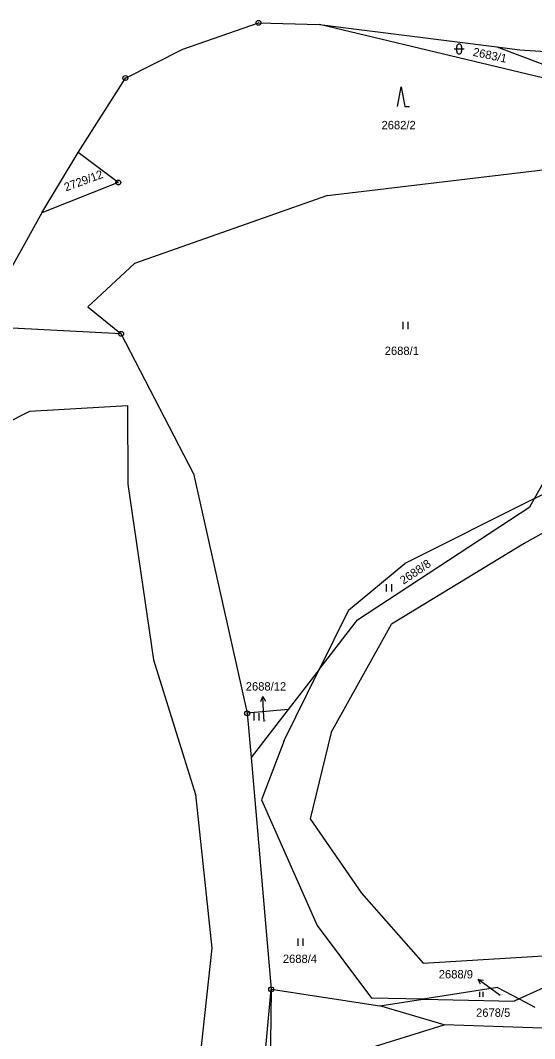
# Model space of a CAD drawing. Extents: x -736345 to -729997, y -1130177 to -1122501.
# Drawn here: x -734447.9 to -734343.4, y -1125281.1 to -1125074.1 of the extents above; entities that cross this region are included whole.
import ezdxf

# ---------------------------------------------------------------- set-up
doc = ezdxf.new("R2010")
doc.units = 0
for name, color, linetype in [('Vrstva 1', 7, 'Continuous'), ('Vrstva 16', 7, 'Continuous'), ('Vrstva 18', 7, 'Continuous'), ('Vrstva 25', 7, 'Continuous'), ('Vrstva 4', 7, 'Continuous')]:
    doc.layers.add(name, color=color, linetype=linetype)

msp = doc.modelspace()

# ---------------------------------------------------------------- linework, layer by layer
at = {"layer": 'Vrstva 1'}
for points in [[(-734414.96, -1125079.9), (-734399.56, -1125074.56)], [(-734399.56, -1125074.56), (-734387.19, -1125074.9)], [(-734321.46, -1125090.64), (-734387.19, -1125074.9)], [(-734387.19, -1125074.9), (-734351.13, -1125079.46)], [(-734426.61, -1125085.79), (-734414.96, -1125079.9)], [(-734351.13, -1125079.46), (-734346.43, -1125080.06)], [(-734351.13, -1125079.46), (-734321.46, -1125090.64)], [(-734346.43, -1125080.06), (-734331.84, -1125081)], [(-734436.2, -1125100.93), (-734426.61, -1125085.79)], [(-734443.56, -1125113.18), (-734436.2, -1125100.93)], [(-734428.05, -1125107.03), (-734436.2, -1125100.93)], [(-734385.56, -1125109.64), (-734338.4, -1125104.03)], [(-734428.05, -1125107.03), (-734443.56, -1125113.18)], [(-734385.56, -1125109.64), (-734424.77, -1125123.48)], [(-734443.56, -1125113.18), (-734454.65, -1125132.96)], [(-734424.77, -1125123.48), (-734434.21, -1125132.31)], [(-734434.21, -1125132.31), (-734427.48, -1125137.8)], [(-734427.48, -1125137.8), (-734454.91, -1125136.4)], [(-734412.8, -1125166.2), (-734427.48, -1125137.8)], [(-734343.47, -1125171.31), (-734332.06, -1125151.15)], [(-734446, -1125153.53), (-734426.15, -1125152.39)], [(-734426.15, -1125152.39), (-734426.09, -1125168.38)], [(-734471.88, -1125166.62), (-734446, -1125153.53)], [(-734343.47, -1125171.31), (-734325.17, -1125162.16)], [(-734412.8, -1125166.2), (-734401.85, -1125214.96)], [(-734426.09, -1125168.38), (-734420.91, -1125204.08)], [(-734343.47, -1125171.31), (-734369.81, -1125184.48)], [(-734344.41, -1125172.97), (-734343.47, -1125171.31)], [(-734379.41, -1125195.95), (-734344.41, -1125172.97)], [(-734381.28, -1125193.99), (-734369.81, -1125184.48)], [(-734381.28, -1125193.99), (-734387.23, -1125206.06)], [(-734387.23, -1125206.06), (-734379.41, -1125195.95)], [(-734420.91, -1125204.08), (-734412.39, -1125231.44)], [(-734394.36, -1125220.51), (-734387.23, -1125206.06)], [(-734387.23, -1125206.06), (-734393.53, -1125214.2)], [(-734393.53, -1125214.2), (-734401.85, -1125214.96)], [(-734401.85, -1125214.96), (-734401.07, -1125223.93)], [(-734393.53, -1125214.2), (-734401.07, -1125223.93)], [(-734394.36, -1125220.51), (-734398.95, -1125232.56)], [(-734401.07, -1125223.93), (-734396.98, -1125271.09)], [(-734412.39, -1125231.44), (-734409.03, -1125262.72)], [(-734398.95, -1125232.56), (-734387.65, -1125258.1)], [(-734387.65, -1125258.1), (-734376.6, -1125272.89)], [(-734409.03, -1125262.72), (-734412.27, -1125292.63)], [(-734329.21, -1125265.17), (-734346.6, -1125273.04)], [(-734401.69, -1125322.03), (-734396.98, -1125271.09)], [(-734396.98, -1125271.09), (-734398.24, -1125375.52)], [(-734396.98, -1125271.09), (-734374.93, -1125274.47)], [(-734351, -1125270.75), (-734366.19, -1125273.11)], [(-734351, -1125270.75), (-734346.6, -1125273.04)], [(-734366.19, -1125273.11), (-734376.6, -1125272.89)], [(-734374.93, -1125274.47), (-734366.19, -1125273.11)], [(-734366.19, -1125273.11), (-734347.63, -1125273.51)], [(-734346.6, -1125273.04), (-734347.63, -1125273.51)], [(-734346.6, -1125273.04), (-734343.42, -1125274.7)], [(-734361.82, -1125278.34), (-734374.93, -1125274.47)], [(-734377.74, -1125283.23), (-734361.82, -1125278.34)], [(-734333.82, -1125279.23), (-734361.82, -1125278.34)]]:
    msp.add_lwpolyline(points, dxfattribs=at)
at = {"layer": 'Vrstva 16'}
for points in [[(-734398.43, -1125216.66), (-734398.53, -1125214.53)], [(-734350.42, -1125272.32), (-734352.5, -1125270.82)]]:
    msp.add_lwpolyline(points, dxfattribs=at)
at = {"layer": 'Vrstva 25'}
for points in [[(-734359.78, -1125079.88), (-734357.78, -1125079.88)], [(-734359.28, -1125080.38), (-734359.28, -1125079.38)], [(-734358.28, -1125079.38), (-734358.28, -1125080.38)], [(-734371.34, -1125091.58), (-734370.59, -1125087.58), (-734369.84, -1125091.58), (-734368.84, -1125091.58)], [(-734370.187, -1125136.855), (-734370.187, -1125135.355)], [(-734369.153, -1125136.855), (-734369.153, -1125135.355)], [(-734373.527, -1125190.205), (-734373.527, -1125188.705)], [(-734372.493, -1125190.205), (-734372.493, -1125188.705)], [(-734399.116, -1125212.554), (-734398.66, -1125211.533), (-734398.118, -1125212.511)], [(-734398.53, -1125214.53), (-734398.66, -1125211.533)], [(-734400.447, -1125216.425), (-734400.447, -1125214.925)], [(-734399.413, -1125216.425), (-734399.413, -1125214.925)], [(-734391.517, -1125262.275), (-734391.517, -1125260.775)], [(-734390.483, -1125262.275), (-734390.483, -1125260.775)], [(-734352.5, -1125270.82), (-734354.933, -1125269.066)], [(-734354.414, -1125270.056), (-734354.933, -1125269.066), (-734353.829, -1125269.245)], [(-734354.596, -1125272.602), (-734354.596, -1125271.597)], [(-734353.903, -1125272.602), (-734353.903, -1125271.597)]]:
    msp.add_lwpolyline(points, dxfattribs=at)
for centre, radius in [((-734399.56, -1125074.56), 0.5), ((-734399.56, -1125074.56), 0.032), ((-734426.61, -1125085.79), 0.5), ((-734426.61, -1125085.79), 0.032), ((-734428.05, -1125107.03), 0.5), ((-734428.05, -1125107.03), 0.032), ((-734427.48, -1125137.8), 0.5), ((-734427.48, -1125137.8), 0.032), ((-734401.85, -1125214.96), 0.5), ((-734401.85, -1125214.96), 0.032), ((-734396.98, -1125271.09), 0.5), ((-734396.98, -1125271.09), 0.032)]:
    msp.add_circle(centre, radius, dxfattribs=at)
for centre, start, end in [((-734358.78, -1125079.38), 0.10099, 180.00143), ((-734358.78, -1125080.38), 180.10243, 0.00286)]:
    msp.add_arc(centre, 0.5, start, end, dxfattribs=at)
at = {"layer": 'Vrstva 4'}
for points in [[(-734321.09, -1125166.72), (-734345.58, -1125180.44)], [(-734345.58, -1125180.44), (-734372.5, -1125196.85)], [(-734384.81, -1125218.88), (-734372.5, -1125196.85)], [(-734384.81, -1125218.88), (-734389.07, -1125236.43)], [(-734389.07, -1125236.43), (-734378.61, -1125251.55)], [(-734378.61, -1125251.55), (-734366.08, -1125265.74)], [(-734366.08, -1125265.74), (-734338.32, -1125264.06)]]:
    msp.add_lwpolyline(points, dxfattribs=at)

# ---------------------------------------------------------------- texts
at = {"layer": 'Vrstva 16'}
for s, p in [('2688/12', (-734402.147, -1125210.34)), ('2688/9', (-734362.927, -1125268.87))]:
    msp.add_text(s, height=1.7, dxfattribs=at).set_placement(p)
at = {"layer": 'Vrstva 18'}
for s, rotation, p in [('2683/1', 348.00277, (-734356.093, -1125081.246)), ('2729/12', 20.10016, (-734438.691, -1125108.854)), ('2688/8', 34.00027, (-734370.097, -1125188.843))]:
    msp.add_text(s, height=1.7, rotation=rotation, dxfattribs=at).set_placement(p)
for s, height, p in [('2682/2', 1.7, (-734374.56, -1125096.2)), ('2688/1', 1.7, (-734373.91, -1125142.1)), ('2688/12', 0.1, (-734398.23, -1125216.46)), ('2688/4', 1.7, (-734394.61, -1125265.73)), ('2688/9', 0.1, (-734350.22, -1125272.12)), ('2678/5', 1.7, (-734355.34, -1125276.68))]:
    msp.add_text(s, height=height, dxfattribs=at).set_placement(p)

doc.saveas('drawing.dxf')
